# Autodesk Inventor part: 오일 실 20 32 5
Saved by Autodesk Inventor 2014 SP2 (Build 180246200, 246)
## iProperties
Created: 2024-04
Part Number: 오일 실 20 32 5
Material: Generic
Document SubType Name: Modeling
Designer: Administrator
Density: 1 g/cm^3
Appearance: Default
Author: Administrator
Author: jhkim
Description: 오일 실 - 비스프링, 조립 GA
Creation Date: 2024-04-08
Sending System: Autodesk Inventor 2025
Preprocessor: ST-DEVELOPER v20
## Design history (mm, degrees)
node "오일 실 20 32 51"
body "Solid1"
node "기준1"
